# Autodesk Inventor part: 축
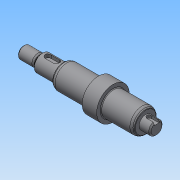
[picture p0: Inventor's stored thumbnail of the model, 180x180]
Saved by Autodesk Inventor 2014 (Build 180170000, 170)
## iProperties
Created: 2020-12
Part Number: 축
Material: 일반
Document SubType Name: Modeling
Designer: NET
Density: 1 g/cm^3
Appearance: 기본값
Author: NET
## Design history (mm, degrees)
sketch "스케치1"
  geometry: L1 (0, 0)-(110, 0); L2 (0, 0)-(0, 5); L3 (0, 5)-(12, 5); L4 (15, 4.8)-(15, 7); L5 (15, 7)-(33, 7); L6 (33, 7)-(33, 10); L7 (101, 10)-(101, 5.5); L8 (101, 5.5)-(110, 5.5); L9 (110, 5.5)-(110, 0); L10 (12, 5)-(13.246, 4.28); L11 (13.546, 4.2)-(14.4, 4.2); L12 (33, 10)-(62, 10); L13 (62, 10)-(62, 13.5); L14 (62, 13.5)-(74, 13.5); L15 (74, 13.5)-(74, 10); L16 (74, 10)-(101, 10); A1 r 0.6 centre (13.546, 4.8) between (13.246, 4.28) and (13.546, 4.2); A2 r 0.6 centre (14.4, 4.8) between (14.4, 4.2) and (15, 4.8)
  constraints: 32 end point, 8 parallel, 5 perpendicular, 4 point on circle, 4 tangent, 2 centre point, 2 collinear, 1 equal radius, 1 horizontal
  dimensions: "d0" = 110 distance of L1.start L1.end; "d2" = 10 diameter of L3 L1; "d4" = 18 distance between parallel lines of L6 L4; "d5" = 14 diameter of L5 L1; "d7" = 11 diameter of L8 L1; "d8" = 150 deg angle of L10 L3; "d9" = 12 distance from line of L3.end L2; "d10" = 0.6 radius of A1; "d11" = 8.4 diameter of L11 L1; "d12" = 9 distance of L7.end L8.end; "d35" = 29 distance between parallel lines of L13 L6; "d36" = 27 distance between parallel lines of L7 L15; "d37" = 12 distance of L13.end L14.end; "d38" = 27 diameter of L14 L1; "d39" = 20 diameter of L12 L1
revolve "회전1" sketch "스케치1" stored, may be unused: angle "d13" = 90 deg
node "작업 평면1"
chamfer "모따기3" distance "d32" = 1; stored, may be unused: second distance "d33" = 2, angle "d34" = 45 deg
sketch "스케치3"
  geometry: L1 (0, 0)-(110, 0); L2 (33, -10)-(33, 10) reference; L3 (33, 10)-(62, 10) reference; L4 (74, -10)-(74, 10) reference; L5 (101, -10)-(101, 10) reference; L6 (101, 8.85)-(99.008, 10); L7 (74, 10)-(101, 10) reference; L8 (33, 10)-(62, 10) reference; L9 (33, 8.85)-(34.992, 10)
  constraints: 6 end point, 4 point on line, 1 horizontal
  dimensions: "d41" = 110 distance of L1.start L1.end; "d43" = 30 deg angle of L7 L6; "d44" = 30 deg angle of L3 L9; "d45" = 17.7 diameter of L9.start L1; "d46" = 17.7 diameter of L6.start L1
revolve "회전6" sketch "스케치3" stored, may be unused: angle "d47" = 90 deg
fillet "모깎기3" dims "d48" = 4
fillet "모깎기4" dims "d49" = 0.5
fillet "모깎기5" dims "d50" = 0.6
sketch "스케치4"
  geometry: C1 r 4.5 at (0, 0) reference; 1 further point
  constraints: 1 vertical alignment
  dimensions: "d51" = 5.5 distance of point (0, -5.5) C1.centre
hole "구멍1" sketch "스케치4" at (0, -5.5) diameter "d52" = 2.459; stored, may be unused: countersink angle "d56" = 90 deg, drill point angle "d58" = 118 deg; dims "d53" = 5, "d54" = 4, "d55" = 2, "d57" = 7
node "작업 평면3"
sketch "스케치6"
  geometry: L1 (-27.5, 0)-(-20.5, 0); L2 (-27.5, -2.5)-(-20.5, -2.5); L3 (-20.5, 2.5)-(-27.5, 2.5); L4 (-33, 8.561)-(-33, -8.561) reference; A1 r 2.5 centre (-27.5, 0) between (-27.5, 2.5) and (-27.5, -2.5); A2 r 2.5 centre (-20.5, 0) between (-20.5, -2.5) and (-20.5, 2.5); 3 further points
  constraints: 8 end point, 4 point on circle, 4 tangent, 2 centre point, 2 midpoint, 1 horizontal, 1 horizontal alignment, 1 parallel
  dimensions: "d66" = 5 diameter of A2; "d68" = 12 dimension on A1 A2; "d69" = 3 distance edge to line of A1 L4
extrude "돌출1" cut sketch "스케치6" distance "d70" = 3; taper "d71" = 0 deg
node "작업 평면4"
sketch "스케치7"
  geometry: L1 (-116, 0)-(-104, 0); L2 (-110, -2)-(-104, -2); L3 (-104, 2)-(-110, 2); L4 (-101, -8.561)-(-101, 8.561) reference; L5 (-110, 2)-(-110, -2); L6 (-110, -4.5)-(-110, 4.5) reference; A1 r 2 centre (-104, 0) between (-104, -2) and (-104, 2); 6 further points
  constraints: 10 end point, 3 midpoint, 2 coincident, 2 point on circle, 2 tangent, 1 centre point, 1 horizontal, 1 parallel
  dimensions: "d74" = 4 diameter of A1; "d76" = 8 dimension on A1 L5; "d77" = 1 distance edge to line of A1 L4
extrude "돌출2" cut sketch "스케치7" distance "d78" = 7; taper "d79" = 0 deg
node "솔리드1"
node "투영된 루프2"
other parameters: "d17" = 0, "d64" = 7
